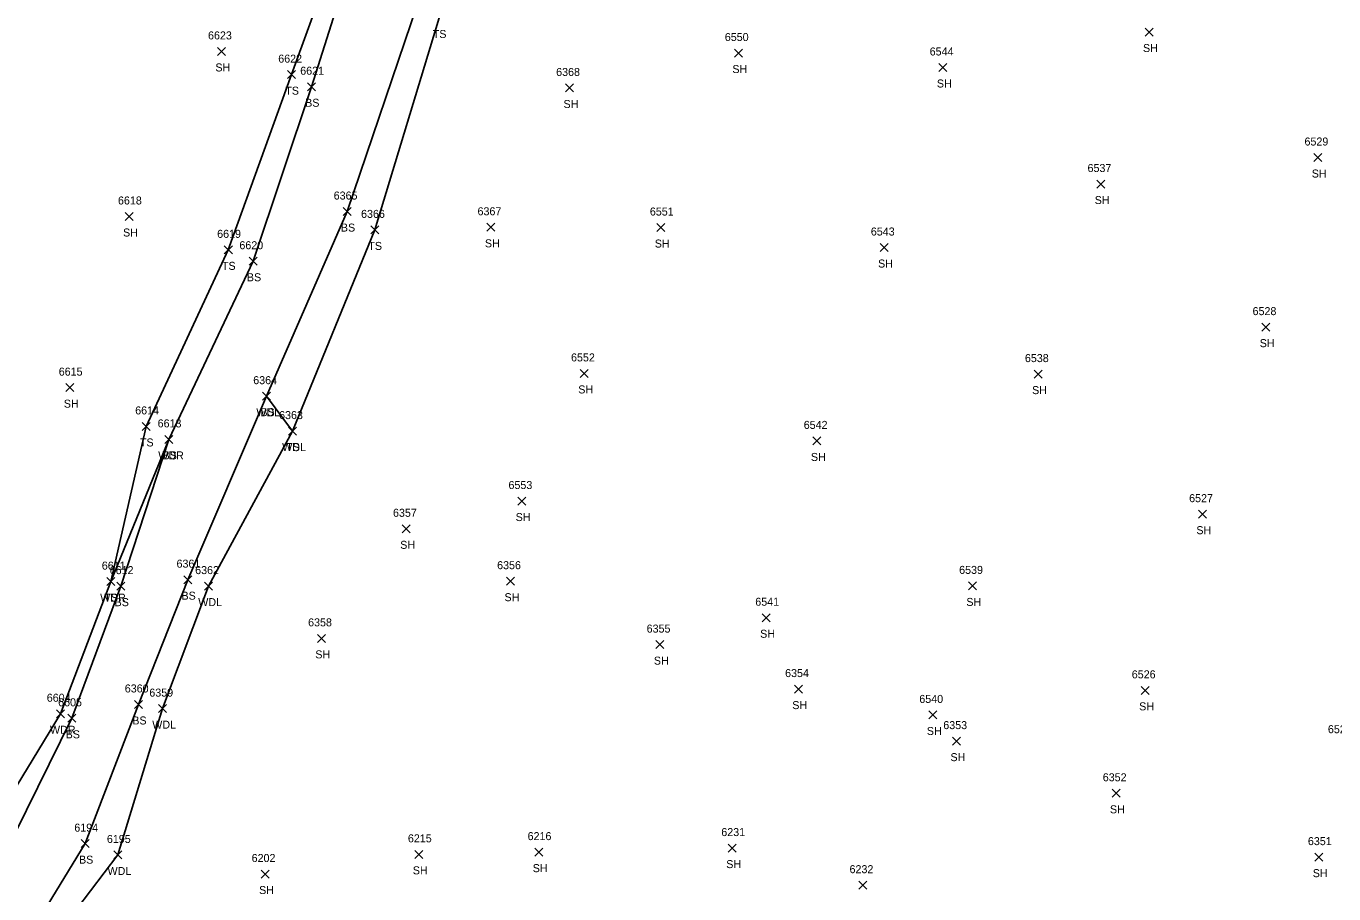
# Model space of a CAD drawing. Extents: x 1678863 to 1683592, y 407783 to 418211.
# Drawn here: x 1679456.9 to 1679783.6, y 409532.2 to 409749 of the extents above; entities that cross this region are included whole.
import ezdxf

# ---------------------------------------------------------------- set-up
doc = ezdxf.new("R2010")
doc.units = 0
for name, color, linetype in [('L_A', 7, 'Continuous'), ('L_I', 7, 'Continuous'), ('L_TIC', 7, 'Continuous'), ('LAWA', 7, 'Continuous'), ('LELB', 7, 'Continuous')]:
    doc.layers.add(name, color=color, linetype=linetype)

msp = doc.modelspace()

# ---------------------------------------------------------------- linework, layer by layer
at = {"layer": 'L_TIC'}
for points in [[(1679736.39, 409746.5), (1679738.39, 409748.5)], [(1679738.39, 409746.5), (1679736.39, 409748.5)], [(1679504.65, 409741.65), (1679506.65, 409743.65)], [(1679506.65, 409741.65), (1679504.65, 409743.65)], [(1679633.81, 409741.25), (1679635.81, 409743.25)], [(1679635.81, 409741.25), (1679633.81, 409743.25)], [(1679522.19, 409735.85), (1679524.19, 409737.85)], [(1679524.19, 409735.85), (1679522.19, 409737.85)], [(1679684.9, 409737.64), (1679686.9, 409739.64)], [(1679686.9, 409737.64), (1679684.9, 409739.64)], [(1679527.12, 409732.83), (1679529.12, 409734.83)], [(1679529.12, 409732.83), (1679527.12, 409734.83)], [(1679591.62, 409732.52), (1679593.62, 409734.52)], [(1679593.62, 409732.52), (1679591.62, 409734.52)], [(1679778.55, 409715.15), (1679780.55, 409717.15)], [(1679780.55, 409715.15), (1679778.55, 409717.15)], [(1679724.33, 409708.53), (1679726.33, 409710.53)], [(1679726.33, 409708.53), (1679724.33, 409710.53)], [(1679481.58, 409700.42), (1679483.58, 409702.42)], [(1679483.58, 409700.42), (1679481.58, 409702.42)], [(1679536.05, 409701.65), (1679538.05, 409703.65)], [(1679538.05, 409701.65), (1679536.05, 409703.65)], [(1679542.94, 409697.07), (1679544.94, 409699.07)], [(1679544.94, 409697.07), (1679542.94, 409699.07)], [(1679571.98, 409697.72), (1679573.98, 409699.72)], [(1679573.98, 409697.72), (1679571.98, 409699.72)], [(1679614.42, 409697.66), (1679616.42, 409699.66)], [(1679616.42, 409697.66), (1679614.42, 409699.66)], [(1679506.37, 409692.09), (1679508.37, 409694.09)], [(1679508.37, 409692.09), (1679506.37, 409694.09)], [(1679670.2, 409692.67), (1679672.2, 409694.67)], [(1679672.2, 409692.67), (1679670.2, 409694.67)], [(1679512.57, 409689.24), (1679514.57, 409691.24)], [(1679514.57, 409689.24), (1679512.57, 409691.24)], [(1679765.57, 409672.78), (1679767.57, 409674.78)], [(1679767.57, 409672.78), (1679765.57, 409674.78)], [(1679595.3, 409661.22), (1679597.3, 409663.22)], [(1679597.3, 409661.22), (1679595.3, 409663.22)], [(1679708.69, 409661.05), (1679710.69, 409663.05)], [(1679710.69, 409661.05), (1679708.69, 409663.05)], [(1679466.79, 409657.67), (1679468.79, 409659.67)], [(1679468.79, 409657.67), (1679466.79, 409659.67)], [(1679515.94, 409655.53), (1679517.94, 409657.53)], [(1679517.94, 409655.53), (1679515.94, 409657.53)], [(1679515.94, 409655.53), (1679517.94, 409657.53)], [(1679517.94, 409655.53), (1679515.94, 409657.53)], [(1679485.88, 409647.98), (1679487.88, 409649.98)], [(1679487.88, 409647.98), (1679485.88, 409649.98)], [(1679491.5, 409644.74), (1679493.5, 409646.74)], [(1679493.5, 409644.74), (1679491.5, 409646.74)], [(1679491.5, 409644.74), (1679493.5, 409646.74)], [(1679493.5, 409644.74), (1679491.5, 409646.74)], [(1679522.4, 409646.81), (1679524.4, 409648.81)], [(1679524.4, 409646.81), (1679522.4, 409648.81)], [(1679522.4, 409646.81), (1679524.4, 409648.81)], [(1679524.4, 409646.81), (1679522.4, 409648.81)], [(1679653.42, 409644.36), (1679655.42, 409646.36)], [(1679655.42, 409644.36), (1679653.42, 409646.36)], [(1679579.66, 409629.34), (1679581.66, 409631.34)], [(1679581.66, 409629.34), (1679579.66, 409631.34)], [(1679749.72, 409626.06), (1679751.72, 409628.06)], [(1679751.72, 409626.06), (1679749.72, 409628.06)], [(1679550.82, 409622.41), (1679552.82, 409624.41)], [(1679552.82, 409622.41), (1679550.82, 409624.41)], [(1679476.98, 409609.21), (1679478.98, 409611.21)], [(1679478.98, 409609.21), (1679476.98, 409611.21)], [(1679476.98, 409609.21), (1679478.98, 409611.21)], [(1679478.98, 409609.21), (1679476.98, 409611.21)], [(1679479.52, 409608.08), (1679481.52, 409610.08)], [(1679481.52, 409608.08), (1679479.52, 409610.08)], [(1679496.22, 409609.7), (1679498.22, 409611.7)], [(1679498.22, 409609.7), (1679496.22, 409611.7)], [(1679501.43, 409608.09), (1679503.43, 409610.09)], [(1679503.43, 409608.09), (1679501.43, 409610.09)], [(1679576.89, 409609.32), (1679578.89, 409611.32)], [(1679578.89, 409609.32), (1679576.89, 409611.32)], [(1679692.26, 409608.14), (1679694.26, 409610.14)], [(1679694.26, 409608.14), (1679692.26, 409610.14)], [(1679640.76, 409600.19), (1679642.76, 409602.19)], [(1679642.76, 409600.19), (1679640.76, 409602.19)], [(1679529.61, 409595.04), (1679531.61, 409597.04)], [(1679531.61, 409595.04), (1679529.61, 409597.04)], [(1679614.19, 409593.48), (1679616.19, 409595.48)], [(1679616.19, 409593.48), (1679614.19, 409595.48)], [(1679648.78, 409582.37), (1679650.78, 409584.37)], [(1679650.78, 409582.37), (1679648.78, 409584.37)], [(1679735.45, 409582.05), (1679737.45, 409584.05)], [(1679737.45, 409582.05), (1679735.45, 409584.05)], [(1679483.94, 409578.53), (1679485.94, 409580.53)], [(1679485.94, 409578.53), (1679483.94, 409580.53)], [(1679464.45, 409576.21), (1679466.45, 409578.21)], [(1679466.45, 409576.21), (1679464.45, 409578.21)], [(1679489.95, 409577.49), (1679491.95, 409579.49)], [(1679491.95, 409577.49), (1679489.95, 409579.49)], [(1679682.39, 409575.91), (1679684.39, 409577.91)], [(1679684.39, 409575.91), (1679682.39, 409577.91)], [(1679467.29, 409575.07), (1679469.29, 409577.07)], [(1679469.29, 409575.07), (1679467.29, 409577.07)], [(1679688.3, 409569.37), (1679690.3, 409571.37)], [(1679690.3, 409569.37), (1679688.3, 409571.37)], [(1679728.14, 409556.34), (1679730.14, 409558.34)], [(1679730.14, 409556.34), (1679728.14, 409558.34)], [(1679470.63, 409543.76), (1679472.63, 409545.76)], [(1679472.63, 409543.76), (1679470.63, 409545.76)], [(1679632.27, 409542.65), (1679634.27, 409544.65)], [(1679634.27, 409542.65), (1679632.27, 409544.65)], [(1679478.77, 409540.93), (1679480.77, 409542.93)], [(1679480.77, 409540.93), (1679478.77, 409542.93)], [(1679553.97, 409541.09), (1679555.97, 409543.09)], [(1679555.97, 409541.09), (1679553.97, 409543.09)], [(1679583.93, 409541.64), (1679585.93, 409543.64)], [(1679585.93, 409541.64), (1679583.93, 409543.64)], [(1679778.82, 409540.39), (1679780.82, 409542.39)], [(1679780.82, 409540.39), (1679778.82, 409542.39)], [(1679515.58, 409536.17), (1679517.58, 409538.17)], [(1679517.58, 409536.17), (1679515.58, 409538.17)], [(1679664.87, 409533.38), (1679666.87, 409535.38)], [(1679666.87, 409533.38), (1679664.87, 409535.38)]]:
    msp.add_lwpolyline(points, dxfattribs=at)
at = {"layer": 'LAWA'}
for points in [[(1679495.82, 410287.8), (1679486.74, 410250.38), (1679478.4, 410206.12), (1679466.45, 410152.28), (1679462.07, 410108.74), (1679451.4, 410063.43), (1679442.8, 410015.27), (1679430.51, 409964.86), (1679414.84, 409904.85), (1679400, 409851.58), (1679387.01, 409795.74), (1679373.8, 409743.1), (1679360.31, 409682.61), (1679353.23, 409617.6), (1679355.41, 409575.65), (1679362.78, 409551.01), (1679388.4, 409540.16), (1679414.21, 409538.82), (1679436.17, 409540.57), (1679448.85, 409550.03), (1679465.45, 409577.21), (1679477.98, 409610.21), (1679492.5, 409645.74)], [(1679462.73, 409519.48), (1679479.77, 409541.93), (1679490.95, 409578.49), (1679502.43, 409609.09), (1679523.4, 409647.81), (1679516.94, 409656.53)]]:
    msp.add_lwpolyline(points, dxfattribs=at)
at = {"layer": 'LELB'}
for points in [[(1679477.98, 409610.21), (1679486.88, 409648.98), (1679507.37, 409693.09), (1679523.19, 409736.85), (1679542.18, 409789.11), (1679561.96, 409835.32), (1679581.04, 409873.51), (1679603.75, 409902.38), (1679633.91, 409920.6), (1679664.9, 409937.31), (1679701.51, 409950.49), (1679753.88, 409959.97)], [(1679454.13, 409547.39), (1679468.29, 409576.07), (1679480.52, 409609.08), (1679492.5, 409645.74), (1679513.57, 409690.24), (1679528.12, 409733.83), (1679545.02, 409787.18), (1679565.1, 409832.69), (1679583.82, 409871.31), (1679607.55, 409898.92), (1679635.47, 409918.42), (1679666.49, 409932.11), (1679704.39, 409943.01), (1679753.59, 409954.93)], [(1679459.09, 409524.34), (1679471.63, 409544.76), (1679484.94, 409579.53), (1679497.22, 409610.7), (1679516.94, 409656.53), (1679537.05, 409702.65), (1679554.59, 409754.46), (1679569.9, 409792.86), (1679589.23, 409846.69), (1679613.01, 409881.68), (1679653.73, 409909.74), (1679693.45, 409927.09), (1679741.04, 409937.55), (1679770.9, 409943.28)], [(1679523.4, 409647.81), (1679543.94, 409698.07), (1679560.04, 409751.01), (1679575.94, 409788.85), (1679593.86, 409843.08), (1679619.13, 409877.09), (1679655.95, 409903.89), (1679694.88, 409922.2), (1679742.19, 409932.34), (1679772.13, 409938.89)]]:
    msp.add_lwpolyline(points, dxfattribs=at)

# ---------------------------------------------------------------- texts
at = {"layer": 'L_A'}
for s, p in [('TS', (1679558.45, 409746.01)), ('SH', (1679735.88, 409742.5)), ('SH', (1679504.14, 409737.65)), ('SH', (1679633.29, 409737.25)), ('SH', (1679684.39, 409733.64)), ('TS', (1679521.6, 409731.85)), ('BS', (1679526.56, 409728.83)), ('SH', (1679591.11, 409728.52)), ('SH', (1679778.04, 409711.15)), ('SH', (1679723.82, 409704.53)), ('SH', (1679481.07, 409696.42)), ('BS', (1679535.49, 409697.65)), ('TS', (1679542.35, 409693.07)), ('SH', (1679571.47, 409693.72)), ('SH', (1679613.91, 409693.66)), ('TS', (1679505.78, 409688.09)), ('SH', (1679669.69, 409688.67)), ('BS', (1679512.01, 409685.24)), ('SH', (1679765.05, 409668.78)), ('SH', (1679594.79, 409657.22)), ('SH', (1679708.18, 409657.05)), ('SH', (1679466.27, 409653.67)), ('WDL', (1679514.36, 409651.53)), ('BS', (1679515.38, 409651.53)), ('TS', (1679485.29, 409643.98)), ('WDR', (1679489.86, 409640.74)), ('BS', (1679490.94, 409640.74)), ('WDL', (1679520.82, 409642.81)), ('TS', (1679521.81, 409642.81)), ('SH', (1679652.91, 409640.36)), ('SH', (1679579.15, 409625.34)), ('SH', (1679749.21, 409622.06)), ('SH', (1679550.31, 409618.41)), ('WDR', (1679475.35, 409605.21)), ('TS', (1679476.39, 409605.21)), ('BS', (1679495.66, 409605.7)), ('SH', (1679576.37, 409605.32)), ('BS', (1679478.96, 409604.08)), ('WDL', (1679499.85, 409604.09)), ('SH', (1679691.75, 409604.14)), ('SH', (1679640.24, 409596.19)), ('SH', (1679529.1, 409591.04)), ('SH', (1679613.68, 409589.48)), ('SH', (1679648.26, 409578.37)), ('SH', (1679734.93, 409578.05)), ('WDR', (1679462.81, 409572.21)), ('BS', (1679483.38, 409574.53)), ('WDL', (1679488.36, 409573.49)), ('SH', (1679681.88, 409571.91)), ('BS', (1679466.73, 409571.07)), ('SH', (1679687.79, 409565.37)), ('SH', (1679727.62, 409552.34)), ('BS', (1679470.07, 409539.76)), ('WDL', (1679477.19, 409536.93)), ('SH', (1679553.46, 409537.09)), ('SH', (1679583.42, 409537.64)), ('SH', (1679631.76, 409538.65)), ('SH', (1679778.3, 409536.39)), ('SH', (1679515.06, 409532.17))]:
    msp.add_text(s, height=2, dxfattribs=at).set_placement(p)
at = {"layer": 'L_I'}
for s, p in [('6623', (1679502.3, 409745.65)), ('6550', (1679631.41, 409745.25)), ('6622', (1679519.84, 409739.85)), ('6544', (1679682.59, 409741.64)), ('6621', (1679525.33, 409736.83)), ('6368', (1679589.27, 409736.52)), ('6529', (1679776.23, 409719.15)), ('6537', (1679722.03, 409712.53)), ('6618', (1679479.8, 409704.42)), ('6365', (1679533.69, 409705.65)), ('6366', (1679540.53, 409701.07)), ('6367', (1679569.63, 409701.72)), ('6551', (1679612.68, 409701.66)), ('6619', (1679504.58, 409696.09)), ('6543', (1679667.89, 409696.67)), ('6620', (1679510.13, 409693.24)), ('6528', (1679763.26, 409676.78)), ('6552', (1679592.99, 409665.22)), ('6538', (1679706.38, 409665.05)), ('6615', (1679465, 409661.67)), ('6364', (1679513.59, 409659.53)), ('6364', (1679513.59, 409659.53)), ('6614', (1679484.1, 409651.98)), ('6363', (1679520.05, 409650.81)), ('6363', (1679520.05, 409650.81)), ('6613', (1679489.71, 409648.74)), ('6613', (1679489.71, 409648.74)), ('6542', (1679651.12, 409648.36)), ('6553', (1679577.36, 409633.34)), ('6527', (1679747.41, 409630.06)), ('6357', (1679548.51, 409626.41)), ('6611', (1679475.76, 409613.21)), ('6611', (1679475.76, 409613.21)), ('6612', (1679477.73, 409612.08)), ('6361', (1679494.43, 409613.7)), ('6362', (1679499.08, 409612.09)), ('6356', (1679574.52, 409613.32)), ('6539', (1679689.95, 409612.14)), ('6541', (1679639.02, 409604.19)), ('6358', (1679527.3, 409599.04)), ('6355', (1679611.88, 409597.48)), ('6354', (1679646.47, 409586.37)), ('6526', (1679733.08, 409586.05)), ('6360', (1679481.5, 409582.53)), ('6604', (1679462.01, 409580.21)), ('6605', (1679464.85, 409579.07)), ('6359', (1679487.63, 409581.49)), ('6540', (1679680, 409579.91)), ('6353', (1679685.99, 409573.37)), ('6525', (1679782.08, 409572.35)), ('6352', (1679725.83, 409560.34)), ('6194', (1679468.89, 409547.76)), ('6231', (1679630.53, 409546.65)), ('6195', (1679477.03, 409544.93)), ('6215', (1679552.23, 409545.09)), ('6216', (1679582.14, 409545.64)), ('6351', (1679777.08, 409544.39)), ('6202', (1679513.19, 409540.17)), ('6232', (1679662.57, 409537.38))]:
    msp.add_text(s, height=2, dxfattribs=at).set_placement(p)

doc.saveas('drawing.dxf')
